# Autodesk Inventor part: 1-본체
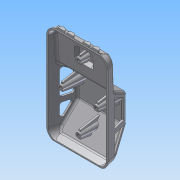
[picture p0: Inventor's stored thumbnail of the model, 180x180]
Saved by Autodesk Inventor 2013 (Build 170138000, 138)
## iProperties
Created: 2015-05
Part Number: 1-본체
Material: ABS 플라스틱
Document SubType Name: Modeling
Designer: Administrator
Density: 1.06 g/cm^3
Mass: 33.3773 g
Surface Area: 309.221 cm^2
Volume: 31.488 cm^3
Author: Administrator
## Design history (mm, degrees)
sketch "스케치1"
  geometry: L1 (-38, 15.5)-(38, 15.5); L2 (38, 15.5)-(38, -15.5); L3 (38, -15.5)-(-38, -15.5); L4 (-38, -15.5)-(-38, 15.5); L5 (-38, 15.5)-(38, -15.5); L6 (38, 15.5)-(-38, -15.5); L7 (38, -15.5)-(29.694, 15.5); L8 (-38, -15.5)-(-29.694, 15.5); 1 further point
  constraints: 16 end point, 2 midpoint, 2 parallel, 2 point on line, 1 horizontal, 1 perpendicular
  dimensions: "d2" = 31 distance between parallel lines of L3 L1; "d4" = 76 distance of L1.start L1.end; "d5" = 105 deg angle of L3 L8; "d6" = 105 deg angle of L3 L7
extrude "돌출1" new body sketch "스케치1" distance "d7" = 122; taper "d8" = 0 deg
node "작업 평면1"
fillet "모깎기1" dims "d97" = 12
sketch "스케치2"
  geometry: L1 (15.5, 12)-(15.5, 110) reference; L2 (-15.5, 12)-(-15.5, 110) reference; L3 (-14.5, 122)-(-14.5, 121); L4 (-14.5, 121)-(-15.5, 121); L5 (-15.5, 1)-(-14.5, 1); L6 (-14.5, 1)-(-14.5, 0); L7 (-14.5, 122)-(-6.5, 119.856); L8 (-6.5, 119.856)-(-4.411, 80); L9 (-4.411, 80)-(15.5, 67.558); L10 (15.5, 67.558)-(15.5, 32.679); L11 (15.5, 32.679)-(-4.5, 2.679); L12 (-4.5, 2.679)-(-14.5, 0); L13 (15.5, 12)-(-15.5, 12) reference; L14 (-15.5, 110)-(15.5, 110) reference; L15 (15.5, 122)-(-15.5, 122) reference; L16 (-15.5, 0)-(15.5, 0) reference; L17 (15.5, 12)-(15.5, 110) reference; L18 (15.5, 12)-(15.5, 0) reference; L19 (15.5, 122)-(15.5, 110) reference; L20 (-15.5, 110)-(-15.5, 122) reference; L21 (-15.5, 0)-(-15.5, 12) reference; L22 (-15.5, 1)-(-15.5, 0); L23 (-15.5, 0)-(-14.5, 0); L24 (-15.5, 121)-(-15.5, 122); L25 (-15.5, 122)-(-14.5, 122); 1 further point
  constraints: 28 end point, 6 point on line, 4 collinear, 2 parallel, 2 perpendicular
  dimensions: "d10" = 1 distance of L3.start L3.end; "d12" = 1 distance of L3.end L4.end; "d13" = 1 distance of L5.start L5.end; "d14" = 1 distance of L5.end L6.end; "d15" = 105 deg angle of L2 L12; "d16" = 105 deg angle of L2 L7; "d17" = 9 distance from line of L2 L7.end; "d18" = 125 deg angle of L9 L8; "d19" = 42 vertical distance of L8.end L3.start; "d21" = 3 deg angle of L2 L8; "d22" = 30 vertical distance of L10.end L11.end; "d23" = 20 horizontal distance of L10.end L11.end
  node "투영된 루프1"
extrude "돌출2" cut sketch "스케치2" stored distance "d24" = 122; taper "d25" = 0 deg
sketch "스케치4"
  geometry: L1 (22.588, 8.441)-(48.588, 8.441); L2 (48.588, 8.441)-(48.588, 28.441); L3 (48.588, 28.441)-(22.588, 28.441); L4 (22.588, 28.441)-(22.588, 8.441); L5 (22.588, 8.441)-(48.588, 28.441); L6 (48.588, 8.441)-(22.588, 28.441); L7 (60.897, -2.559)-(10.28, -2.559) reference; 5 further points
  constraints: 12 end point, 3 midpoint, 2 parallel, 1 horizontal, 1 perpendicular, 1 vertical alignment
  dimensions: "d31" = 26 distance of L2.end L3.end; "d33" = 20 distance of L1.end L2.end; "d34" = 11 distance between parallel lines of L7 L1
extrude "돌출4" join sketch "스케치4" distance "d35" = 5; taper "d36" = -20 deg
feature "쉘1" dims "d28" = 2
extrude "돌출3" cut sketch "스케치2" stored distance "d29" = 1; taper "d30" = 0 deg
sketch "스케치5"
  geometry: L1 (-4.5, 74.16)-(10.5, 64.787); L2 (10.5, 64.787)-(10.5, 40.16); L3 (10.5, 40.16)-(-4.5, 40.16); L4 (-4.5, 40.16)-(-4.5, 74.16); L5 (15.5, 32.679)-(15.5, 67.558) reference; L6 (15.5, 67.558)-(-4.411, 80) reference; L7 (1.714, 12)-(15.5, 32.679) reference; L8 (10.5, 34.193)-(-4.5, 34.193); L9 (-4.5, 34.193)-(-4.5, 11.693); L10 (-4.5, 11.693)-(10.5, 34.193); 2 further points
  constraints: 14 end point, 4 perpendicular, 2 parallel, 1 vertical
  dimensions: "d39" = 34 distance of L3.end L1.start; "d41" = 15 distance of L2.end L3.end; "d42" = 5 distance between parallel lines of L5 L2; "d45" = 5 distance between parallel lines of L6 L1; "d46" = 15 distance of L8.start L8.end; "d47" = 5 distance from line of L5 L8.start; "d48" = 5 distance between parallel lines of L7 L10
extrude "돌출5" cut sketch "스케치5" stored distance "d49" = 1; taper "d50" = 0 deg
node "작업 평면2"
sketch "스케치6"
  geometry: L1 (12.691, -1)-(63.309, -1) reference; L2 (7.458, 0)-(68.542, 0) reference; C1 r 3 at (38, 20); C2 r 3 at (16, 60); C3 r 3 at (60, 60); C4 r 3 at (38, 100); 6 further points
  constraints: 4 centre point, 3 equal radius, 2 vertical alignment, 1 horizontal alignment, 1 midpoint
  dimensions: "d52" = 21 distance from line of L1 C1.centre; "d53" = 40 vertical distance of C1.centre C3.centre; "d54" = 40 vertical distance of C3.centre C4.centre; "d55" = 6 diameter of C4; "d56" = 44 distance of C3.centre C2.centre; "d57" = 22 horizontal distance of C1.centre C2.centre
extrude "돌출6" join sketch "스케치6" stored distance "d58" = 30; taper "d59" = 4 deg
sketch "스케치7"
  geometry: L1 (-2.184, 94.828)-(-2.894, 108.368) reference; L2 (-14.5, 104)-(-2.708, 104.825) reference; L3 (-14.5, 98)-(-2.306, 97.147) reference; L4 (-14.5, 24)-(8.376, 25.6) reference; L5 (-14.5, 18)-(2.517, 16.81) reference; L6 (-0.69, 12)-(13.5, 33.285) reference; L7 (-14.5, 18)-(-14.5, 24) reference; L8 (-14.5, 98)-(-14.5, 104) reference; L9 (-12.5, 106)-(-12.5, 96); L10 (-12.5, 106)-(-1.472, 107.944); L11 (-1.472, 107.944)-(-1.472, 94.056); L12 (-1.472, 94.056)-(-12.5, 96); L13 (-12.5, 26)-(-12.5, 16); L14 (-12.5, 16)-(0.399, 13.634); L15 (11.332, 30.033)-(-12.5, 26); L16 (11.332, 30.033)-(0.399, 13.634); 6 further points
  constraints: 16 end point, 4 midpoint, 2 horizontal alignment, 2 parallel, 2 point on line, 1 collinear, 1 equal length, 1 vertical
  dimensions: "d60" = 20 deg angle of L12 L10; "d61" = 2 distance between parallel lines of L8 L9; "d62" = 10 distance of L9.start L9.end; "d64" = 13.88898 distance of L10.end L11.end; "d65" = 20 deg angle of L14 L15; "d66" = 2 distance between parallel lines of L7 L13; "d67" = 10 distance of L13.start L13.end; "d68" = 46.7058 deg angle of L16 L15
extrude "돌출7" join sketch "스케치7" stored distance "d69" = 2; taper "d70" = 0 deg
node "작업 평면3"
sketch "스케치8"
  geometry: L1 (13.5, 33.285)-(13.5, 66.449) reference; L2 (-14.5, 58)-(-14.5, 64) reference; L3 (13.5, 56.042)-(13.5, 65.958) reference; L4 (-14.5, 58)-(13.5, 56.042) reference; L5 (-14.5, 64)-(13.5, 65.958) reference; L6 (-12.5, 66)-(-12.5, 56); L7 (-12.5, 56)-(13.5, 51.415); L8 (8.339, 69.674)-(-12.5, 66); L9 (13.5, 66.449)-(-6.354, 78.856) reference; L10 (-12.5, 61)-(20.878, 61); 2 further points
  constraints: 8 end point, 2 midpoint, 2 point on line, 1 horizontal alignment, 1 parallel, 1 perpendicular
  dimensions: "d72" = 20 deg angle of L7 L8; "d73" = 2 distance between parallel lines of L2 L6; "d74" = 10 distance of L6.start L6.end; "d75" = 10 deg angle of L7 L10
extrude "돌출8" join sketch "스케치8" stored distance "d76" = 2; taper "d77" = 0 deg
sketch "스케치9"
  geometry: C1 r 3 at (16, 60) reference; C2 r 3 at (60, 60) reference; C3 r 3 at (38, 100) reference; C4 r 3 at (38, 20) reference; 5 further points
  constraints: 4 coincident
hole "구멍1" sketch "스케치9" at (16, 60), (60, 60), (38, 100), (38, 20) diameter "d78" = 3.242; stored, may be unused: countersink angle "d82" = 90 deg, drill point angle "d84" = 118 deg; dims "d79" = 9, "d80" = 4, "d81" = 2, "d83" = 11
sketch "스케치10"
  geometry: L1 (4.385, 32.679)-(55.002, 32.679) reference; 4 further points
  constraints: 1 vertical alignment, 1 other
  dimensions: "d85" = 50 distance from line of L1 point (29.694, -17.321)
feature "엠보싱1" sketch "스케치10" dims "d2" = 31, "d4" = 76, "d5" = 105 deg, "d6" = 105 deg, "d17" = 9, "d86" = 0.5, "d87" = 0
node "작업 평면4"
sketch "스케치11"
  geometry: A1 r 4 centre (-21, -14.5) between (-17, -14.5) and (-25, -14.5); A2 r 4 centre (-10, -14.5) between (-6, -14.5) and (-14, -14.5); A3 r 4 centre (10, -14.5) between (14, -14.5) and (6, -14.5); A4 r 4 centre (21, -14.5) between (25, -14.5) and (17, -14.5); 5 further points
  constraints: 8 point on circle, 4 centre point, 3 equal radius, 13 other
  dimensions: "d89" = 11 distance of A4.centre A3.centre; "d91" = 11 distance of A2.centre A1.centre; "d92" = 20 distance of A3.centre A2.centre; "d93" = 4 radius of A1; "d94" = 10 horizontal distance of point (0, 0) A2.centre
extrude "돌출9" join sketch "스케치11" stored distance "d95" = 2; taper "d96" = 0 deg
fillet "모깎기2" dims "d98" = 3
fillet "모깎기3" dims "d99" = 3
fillet "모깎기4" dims "d100" = 3
node "솔리드1"
mirror "대칭1"
node "투영된 루프3"
node "투영된 루프4"
node "투영된 루프5"
other parameters: "d9" = 38, "d51" = -1, "d71" = 22, "d88" = 124
